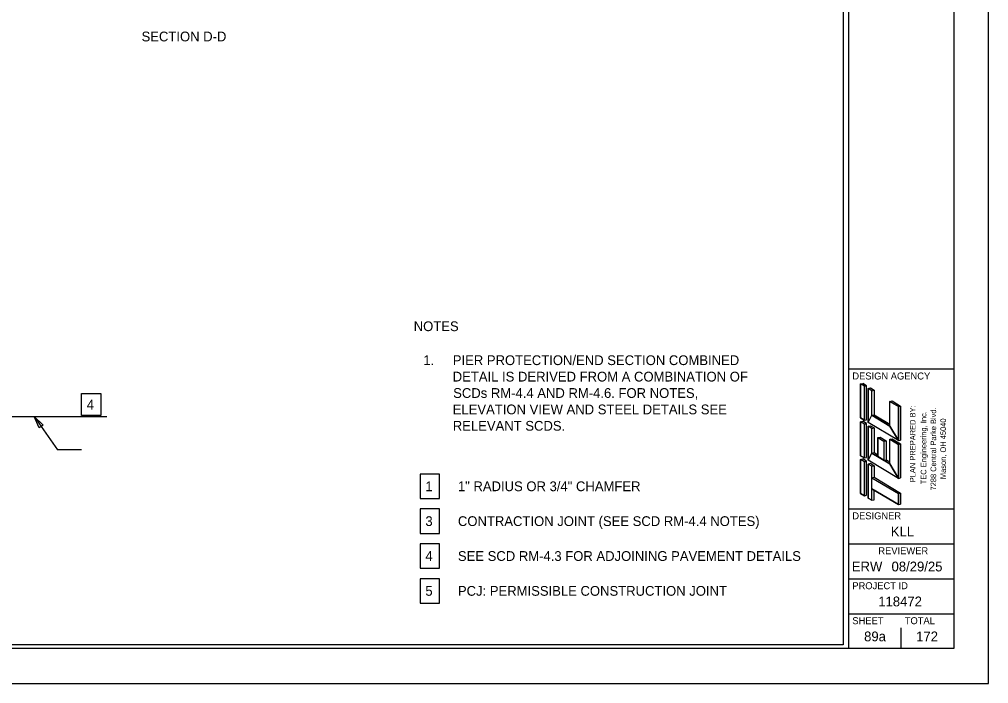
# Model space of a CAD drawing. Extents: x 0 to 680, y 0 to 440.
# Drawn here: x 402.6 to 680, y 0 to 190 of the extents above; entities that cross this region are included whole.
import ezdxf

# ---------------------------------------------------------------- set-up
doc = ezdxf.new("R2010")
doc.units = 0
for name, color, linetype in [('_CIVIL_CONSTRUCTION', 7, 'Continuous'), ('Default', 7, 'Continuous'), ('RD_P_GR_Lt', 7, 'Continuous'), ('RD_P_GR_Rt', 7, 'Continuous'), ('SH_Named_Boundary', 7, 'Continuous')]:
    doc.layers.add(name, color=color, linetype=linetype)

msp = doc.modelspace()

# ---------------------------------------------------------------- linework, layer by layer
at = {"layer": '_CIVIL_CONSTRUCTION'}
msp.add_lwpolyline([(0, 0), (680, 0), (680, 440), (0, 440)], close=True, dxfattribs=at)
at = {"layer": 'Default'}
for p, q in [((367.83, 76.4), (427.69, 76.4)), ((406.88, 76.4), (413.5, 66.92)), ((420.45, 66.92), (413.5, 66.92))]:
    msp.add_line(p, q, dxfattribs=at)
for points in [[(30, 430), (638.4, 430), (638.4, 11.08), (30, 11.08)], [(425.91, 76.71), (420.45, 76.71), (420.45, 82.98), (425.91, 82.98)], [(408.29, 73.13), (406.88, 76.4), (409.45, 73.93)], [(517.33, 52.96), (522.87, 52.96), (522.87, 59.94), (517.33, 59.94)], [(517.33, 42.98), (522.87, 42.98), (522.87, 49.97), (517.33, 49.97)], [(517.33, 33.01), (522.87, 33.01), (522.87, 39.99), (517.33, 39.99)], [(517.33, 23.03), (522.87, 23.03), (522.87, 30.01), (517.33, 30.01)]]:
    msp.add_lwpolyline(points, close=True, dxfattribs=at)
at = {"layer": 'RD_P_GR_Lt'}
for p, q in [((640, 10), (640, 430)), ((640, 90), (670, 90)), ((640, 50), (670, 50)), ((640, 40), (670, 40)), ((640, 30), (670, 30)), ((640, 20), (670, 20))]:
    msp.add_line(p, q, dxfattribs=at)
msp.add_lwpolyline([(30, 430), (670, 430), (670, 10), (30, 10)], close=True, dxfattribs=at)
at = {"layer": 'RD_P_GR_Rt'}
for p, q in [((655, 70), (655, 70)), ((655, 10), (655, 16)), ((647.5, 13.5), (647.5, 13.5))]:
    msp.add_line(p, q, dxfattribs=at)
at = {"layer": 'SH_Named_Boundary'}
for p, q in [((643.38, 85.71), (644.02, 85.87)), ((643.38, 75.99), (643.38, 85.71)), ((644.46, 85.06), (643.38, 85.71)), ((645.1, 85.22), (644.02, 85.87)), ((644.46, 85.06), (645.1, 85.22)), ((644.46, 75.34), (644.46, 85.06)), ((645.1, 75.5), (645.1, 85.22)), ((645.54, 84.41), (646.18, 84.58)), ((646.62, 83.77), (645.54, 84.41)), ((645.54, 74.69), (645.54, 84.41)), ((646.18, 84.58), (647.26, 83.93)), ((646.62, 83.77), (647.26, 83.93)), ((646.62, 76.75), (646.62, 83.77)), ((647.26, 83.93), (647.26, 76.91)), ((651.75, 80.69), (652.39, 80.85)), ((651.75, 73.67), (651.75, 80.69)), ((654.18, 79.23), (651.75, 80.69)), ((652.39, 80.85), (654.82, 79.39)), ((654.18, 79.23), (654.82, 79.39)), ((654.18, 69.51), (654.18, 79.23)), ((654.82, 79.39), (654.82, 69.67)), ((644.46, 75.34), (643.38, 75.99)), ((643.38, 74.91), (644.02, 75.07)), ((643.38, 65.19), (643.38, 74.91)), ((644.46, 74.26), (643.38, 74.91)), ((645.09, 74.45), (644.02, 75.07)), ((644.46, 75.34), (645.1, 75.5)), ((646.62, 76.75), (647.26, 76.91)), ((651.75, 73.67), (646.62, 76.75)), ((647.26, 76.91), (651.75, 74.22)), ((644.46, 74.26), (645.09, 74.45)), ((644.46, 64.54), (644.46, 74.26)), ((645.09, 64.73), (645.09, 74.45)), ((654.18, 69.51), (645.54, 74.69)), ((645.54, 73.61), (646.18, 73.78)), ((645.54, 63.89), (645.54, 73.61)), ((646.62, 72.97), (645.54, 73.61)), ((646.18, 73.78), (647.26, 73.13)), ((646.62, 72.97), (647.26, 73.13)), ((646.62, 65.95), (646.62, 72.97)), ((647.26, 73.13), (647.26, 66.11)), ((648.3, 70.38), (648.95, 70.54)), ((648.3, 70.38), (648.3, 64.93)), ((648.3, 70.38), (650.06, 69.33)), ((648.95, 70.54), (650.71, 69.49)), ((650.06, 69.33), (650.71, 69.49)), ((650.71, 69.49), (650.71, 64.04)), ((651.75, 69.89), (652.39, 70.05)), ((651.75, 62.87), (651.75, 69.89)), ((654.18, 68.43), (651.75, 69.89)), ((652.39, 70.05), (654.82, 68.59)), ((654.18, 69.51), (654.82, 69.67)), ((650.06, 69.33), (650.06, 63.88)), ((654.18, 68.43), (654.82, 68.59)), ((654.18, 58.71), (654.18, 68.43)), ((654.82, 68.59), (654.82, 58.87)), ((644.46, 64.54), (643.38, 65.19)), ((643.38, 64.11), (644.01, 64.3)), ((643.38, 54.39), (643.38, 64.11)), ((644.46, 63.46), (643.38, 64.11)), ((645.1, 63.62), (644.01, 64.3)), ((644.46, 64.54), (645.09, 64.73)), ((654.18, 58.71), (645.54, 63.89)), ((646.62, 65.95), (647.26, 66.11)), ((648.3, 64.93), (646.62, 65.95)), ((647.26, 66.11), (648.3, 65.48)), ((650.06, 63.88), (650.71, 64.04)), ((651.75, 62.87), (650.06, 63.88)), ((650.71, 64.04), (651.75, 63.42)), ((644.45, 63.47), (645.1, 63.62)), ((644.46, 53.74), (644.46, 63.46)), ((645.1, 53.9), (645.1, 63.62)), ((645.54, 62.81), (646.17, 63.03)), ((646.62, 62.17), (645.54, 62.81)), ((645.54, 53.09), (645.54, 62.81)), ((646.17, 63.03), (647.26, 62.33)), ((646.62, 62.17), (647.26, 62.33)), ((646.62, 58.88), (646.62, 62.17)), ((647.26, 62.33), (647.26, 59.04)), ((646.62, 58.88), (647.26, 59.04)), ((646.62, 58.88), (654.18, 54.34)), ((647.26, 59.04), (654.82, 54.51)), ((654.18, 58.71), (654.82, 58.87)), ((646.62, 55.73), (654.18, 51.19)), ((646.62, 52.45), (646.62, 55.73)), ((644.46, 53.74), (643.38, 54.39)), ((644.46, 53.74), (645.1, 53.9)), ((646.62, 52.45), (645.54, 53.09)), ((647.26, 52.61), (647.26, 55.34)), ((654.18, 54.34), (654.82, 54.51)), ((654.18, 51.19), (654.18, 54.34)), ((654.82, 54.51), (654.82, 51.36)), ((646.62, 52.45), (647.26, 52.61)), ((654.18, 51.19), (654.82, 51.36))]:
    msp.add_line(p, q, dxfattribs=at)
for points in [[(643.38, 75.99), (644.46, 75.34), (644.46, 85.06), (643.38, 85.71)], [(645.54, 74.69), (646.62, 76.75), (646.62, 83.77), (645.54, 84.41)], [(654.18, 69.51), (651.75, 73.67), (651.75, 80.69), (654.18, 79.23)], [(643.38, 65.19), (644.46, 64.54), (644.46, 74.26), (643.38, 74.91)], [(645.54, 74.69), (646.62, 76.75), (651.75, 73.67), (654.18, 69.51)], [(645.54, 63.89), (646.62, 65.95), (646.62, 72.97), (645.54, 73.61)], [(648.3, 64.93), (648.3, 70.38), (650.06, 69.33), (650.06, 63.88)], [(654.18, 58.71), (651.75, 62.87), (651.75, 69.89), (654.18, 68.43)], [(643.38, 54.39), (644.46, 53.74), (644.46, 63.46), (643.38, 64.11)], [(645.54, 63.89), (646.62, 65.95), (651.75, 62.87), (654.18, 58.71)], [(645.54, 53.09), (646.62, 52.45), (646.62, 62.17), (645.54, 62.81)], [(646.62, 55.73), (646.62, 58.88), (654.18, 54.34), (654.18, 51.19)]]:
    msp.add_lwpolyline(points, close=True, dxfattribs=at)

# ---------------------------------------------------------------- texts
at = {"layer": 'Default'}
for s, height, p in [('SECTION D-D', 2.7931, (437.6, 183.72)), ('NOTES', 2.793, (515.48, 100.83)), ('1.', 2.793, (518.24, 91.12)), ('PIER PROTECTION/END SECTION COMBINED', 2.7931, (526.66, 91.12)), ('DETAIL IS DERIVED FROM A COMBINATION OF', 2.7931, (526.64, 86.42)), ('SCDs RM-4.4 AND RM-4.6. FOR NOTES,', 2.7931, (526.77, 81.73)), ('4', 2.79, (421.92, 78.41)), ('ELEVATION VIEW AND STEEL DETAILS SEE', 2.7931, (526.64, 77.04)), ('RELEVANT SCDS.', 2.7931, (526.66, 72.35)), ('1', 2.79, (518.82, 55.05)), ('1" RADIUS OR 3/4" CHAMFER', 2.7931, (528.13, 55.05)), ('3', 2.79, (518.82, 45.08)), ('CONTRACTION JOINT (SEE SCD RM-4.4 NOTES)', 2.7931, (528.13, 45.08)), ('4', 2.79, (518.82, 35.1)), ('SEE SCD RM-4.3 FOR ADJOINING PAVEMENT DETAILS', 2.7931, (528.13, 35.1)), ('5', 2.79, (518.82, 25.13)), ('PCJ: PERMISSIBLE CONSTRUCTION JOINT', 2.7931, (528.13, 25.13))]:
    msp.add_text(s, height=height, dxfattribs=at).set_placement(p)
at = {"layer": 'RD_P_GR_Rt'}
for s, height, p in [('DESIGN AGENCY', 2, (641, 87)), ('DESIGNER', 2, (641, 47)), ('KLL', 2.8, (652.02, 42.1)), ('REVIEWER', 2, (648.44, 37)), ('ERW', 2.8, (640.85, 32.1)), ('08/29/25', 2.8, (652.22, 32.1)), ('PROJECT ID', 2, (641, 27)), ('118472', 2.8, (648.42, 22.1)), ('SHEET', 2, (641, 17)), ('TOTAL', 2, (656, 17)), ('89a', 2.8, (644.37, 12.1)), ('172', 2.8, (659.27, 12.1))]:
    msp.add_text(s, height=height, dxfattribs=at).set_placement(p)
at = {"layer": 'SH_Named_Boundary'}
for s, p in [('PLAN PREPARED BY:', (659.07, 57.6)), ('TEC Engineering, Inc.', (662.19, 57.01)), ('7288 Central Parke Blvd.', (664.99, 55.24)), ('Mason, OH 45040', (667.79, 58.49))]:
    msp.add_text(s, height=1.6, rotation=90, dxfattribs=at).set_placement(p)

doc.saveas('drawing.dxf')
